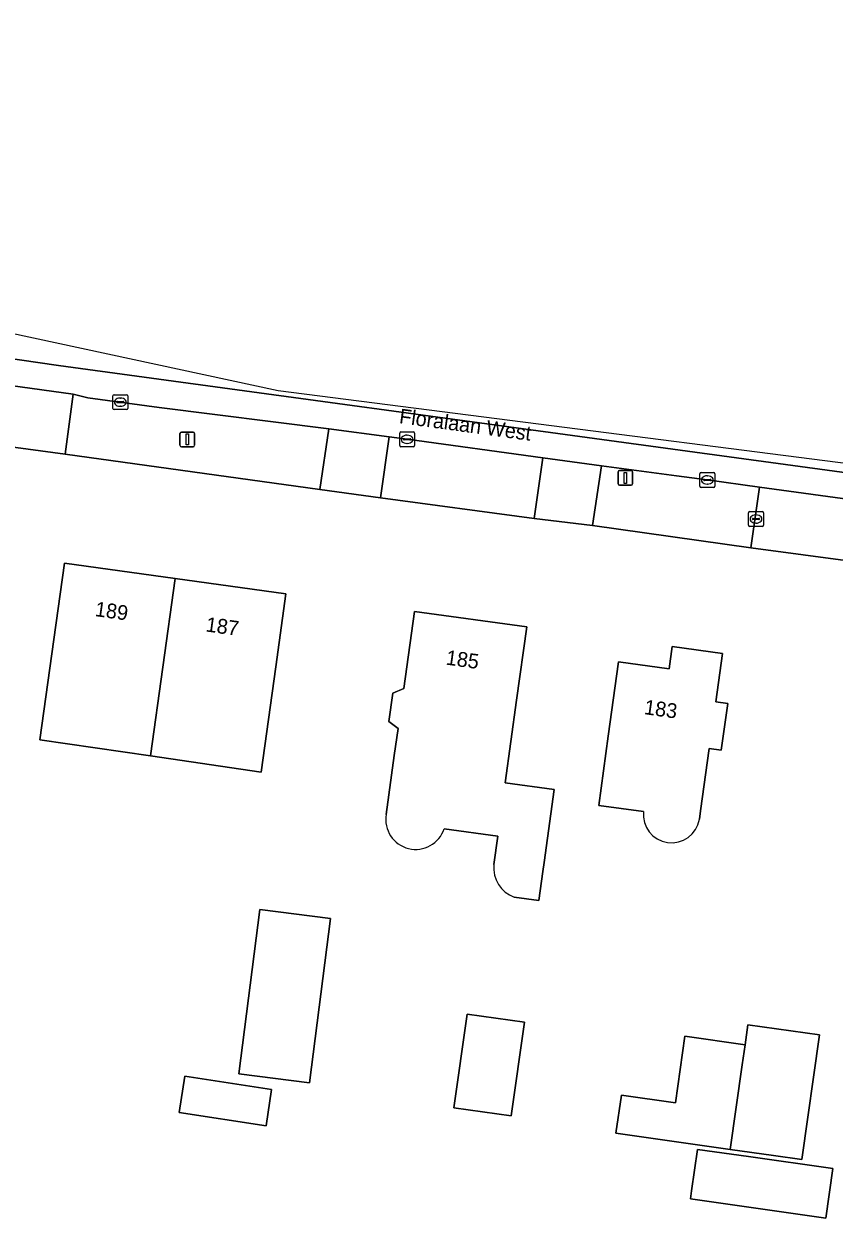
# Model space of a CAD drawing. Extents: x 161483 to 162250, y 379484 to 380833.
# Drawn here: x 161842.7 to 161897.6, y 380748.1 to 380829.1 of the extents above; entities that cross this region are included whole.
import ezdxf

# ---------------------------------------------------------------- set-up
doc = ezdxf.new("R2010")
doc.units = 0
for name, color, linetype in [('IMGEO_Brandkraan', 7, 'Continuous'), ('IMGEO_Erf', 7, 'Continuous'), ('IMGEO_Fietspad_open', 7, 'Continuous'), ('IMGEO_Kolk', 7, 'Continuous'), ('IMGEO_Lichtmast', 7, 'Continuous'), ('IMGEO_Openbare_ruimte_label', 7, 'Continuous'), ('IMGEO_Pand', 7, 'Continuous'), ('IMGEO_Pand_nummerreeks', 7, 'Continuous'), ('IMGEO_Rijbaan_lokaal_gesloten', 7, 'Continuous'), ('IMGEO_Voetpad_open', 7, 'Continuous')]:
    doc.layers.add(name, color=color, linetype=linetype)

msp = doc.modelspace()

# ---------------------------------------------------------------- linework, layer by layer
at = {"layer": 'IMGEO_Brandkraan'}
for p, q in [((161891.846, 380795.091), (161891.846, 380795.943)), ((161891.921, 380796.017), (161892.773, 380796.017)), ((161892.105, 380795.511), (161892.105, 380795.523)), ((161892.543, 380795.474), (161892.145, 380795.474)), ((161892.148, 380795.56), (161892.546, 380795.56)), ((161892.357, 380795.237), (161892.332, 380795.237)), ((161892.334, 380795.797), (161892.359, 380795.797)), ((161892.589, 380795.523), (161892.589, 380795.511)), ((161892.847, 380795.943), (161892.847, 380795.091)), ((161892.773, 380795.017), (161891.921, 380795.017))]:
    msp.add_line(p, q, dxfattribs=at)
for points in [[(161891.846, 380795.091), (161891.846, 380795.943)], [(161891.921, 380796.017), (161892.773, 380796.017)], [(161892.847, 380795.943), (161892.847, 380795.091)], [(161892.773, 380795.017), (161891.921, 380795.017)]]:
    msp.add_lwpolyline(points, dxfattribs=at)
for centre, radius, start, end in [((161891.923, 380795.941), 0.0765, 91.55205, 178.44795), ((161891.923, 380795.941), 0.0765, 91.55205, 178.44795), ((161892.145, 380795.52), 0.0403, 85.87752, 175.75265), ((161892.142, 380795.51), 0.0366, 178.93798, 274.71019), ((161892.546, 380795.517), 0.043, 264.86636, 352.45326), ((161892.55, 380795.522), 0.0386, 1.73085, 96.63898), ((161892.771, 380795.941), 0.0765, 1.55205, 88.44795), ((161892.771, 380795.941), 0.0765, 1.55205, 88.44795), ((161891.923, 380795.093), 0.0765, 181.55205, 268.44795), ((161891.923, 380795.093), 0.0765, 181.55205, 268.44795), ((161892.771, 380795.093), 0.0765, 271.55205, 358.44795), ((161892.771, 380795.093), 0.0765, 271.55205, 358.44795)]:
    msp.add_arc(centre, radius, start, end, dxfattribs=at)
for centre, major_axis, ratio, start_param, end_param in [((161892.333, 380795.517), (-0.387, 0.002), 0.722429, 4.712389, 7.853982), ((161892.358, 380795.517), (-0.39, 0.002), 0.717154, 1.570796, 4.712389)]:
    msp.add_ellipse(centre, major_axis=major_axis, ratio=ratio, start_param=start_param, end_param=end_param, dxfattribs=at)
at = {"layer": 'IMGEO_Erf'}
for points in [[(161947.776, 380785.993), (161943.772, 380786.523), (161932.427, 380787.968), (161928.533, 380788.644), (161917.439, 380790.128), (161913.448, 380790.714), (161899.09, 380792.619), (161891.993, 380793.568), (161881.272, 380795.068), (161877.324, 380795.561), (161866.903, 380796.964), (161862.786, 380797.518), (161845.524, 380799.914), (161837.657, 380800.986)], [(161867.284, 380775.488), (161867.837, 380779.481), (161868.089, 380781.301), (161867.463, 380781.788), (161867.731, 380783.715), (161868.492, 380784.025), (161869.216, 380789.248), (161876.81, 380788.195), (161876.123, 380783.243), (161875.346, 380777.637)], [(161884.718, 380775.679), (161881.69, 380776.099), (161882.339, 380780.782), (161883.04, 380785.836), (161886.458, 380785.361), (161886.668, 380786.872), (161890.078, 380786.399), (161889.622, 380783.111), (161890.436, 380782.998), (161889.999, 380779.842), (161889.175, 380779.957), (161888.587, 380775.717)], [(161875.346, 380777.637), (161878.675, 380777.176), (161877.989, 380772.224), (161877.906, 380771.621), (161877.634, 380769.645), (161875.969, 380769.875)], [(161888.587, 380775.717), (161888.509, 380775.153)], [(161874.578, 380772.081), (161874.845, 380774.016), (161871.216, 380774.518)]]:
    msp.add_lwpolyline(points, dxfattribs=at)
for points in [[(161859.81, 380785.497), (161858.818, 380778.346), (161851.32, 380779.45), (161843.819, 380780.554), (161844.762, 380787.352), (161845.481, 380792.531), (161852.988, 380791.49), (161860.496, 380790.449)], [(161862.083, 380757.292), (161857.301, 380757.904), (161858.726, 380769.034), (161863.508, 380768.422)], [(161875.767, 380755.034), (161871.873, 380755.587), (161872.775, 380761.943), (161876.67, 380761.39)], [(161895.46, 380752.079), (161893.543, 380752.352), (161890.604, 380752.769), (161882.861, 380753.868), (161883.229, 380756.457), (161886.893, 380755.937), (161887.534, 380760.448), (161891.612, 380759.869), (161891.805, 380761.223), (161896.661, 380760.534)], [(161859.143, 380754.376), (161853.256, 380755.282), (161853.635, 380757.742), (161859.522, 380756.836)], [(161897.549, 380751.471), (161897.071, 380748.109), (161887.912, 380749.411), (161887.989, 380749.951), (161888.39, 380752.773), (161891.831, 380752.284)]]:
    msp.add_lwpolyline(points, close=True, dxfattribs=at)
for centre, radius, start, end in [((161869.285, 380775.143), 2.03, 170.2125, 342.07187), ((161886.622, 380775.476), 1.915, 173.92875, 350.27258), ((161876.696, 380771.875), 2.128, 174.44816, 250.01905)]:
    msp.add_arc(centre, radius, start, end, dxfattribs=at)
at = {"layer": 'IMGEO_Fietspad_open'}
for points in [[(161944.816, 380792.342), (161887.22, 380800.191), (161845.075, 380805.921), (161833.402, 380807.634), (161828.42, 380808.407)], [(161838.216, 380805.069), (161846.078, 380803.976), (161847.071, 380803.724), (161851.906, 380803.091), (161863.408, 380801.636), (161867.481, 380801.087), (161868.7, 380800.923), (161877.899, 380799.667), (161881.879, 380799.119), (161886.971, 380798.442), (161889.046, 380798.166), (161892.587, 380797.666), (161899.699, 380796.708), (161912.838, 380794.902), (161914.017, 380794.744), (161918.055, 380794.201), (161929.077, 380792.694), (161932.993, 380792.169), (161935.206, 380791.883), (161944.345, 380790.629), (161948.316, 380790.073)]]:
    msp.add_lwpolyline(points, dxfattribs=at)
at = {"layer": 'IMGEO_Kolk'}
for p, q in [((161848.765, 380803.017), (161848.765, 380803.869)), ((161848.84, 380803.943), (161849.692, 380803.943)), ((161849.024, 380803.437), (161849.024, 380803.449)), ((161849.462, 380803.4), (161849.064, 380803.4)), ((161849.067, 380803.486), (161849.465, 380803.486)), ((161849.253, 380803.723), (161849.278, 380803.723)), ((161849.508, 380803.449), (161849.508, 380803.437)), ((161849.766, 380803.869), (161849.766, 380803.017)), ((161849.692, 380802.943), (161848.84, 380802.943)), ((161849.276, 380803.163), (161849.251, 380803.163)), ((161868.203, 380800.496), (161868.203, 380801.348)), ((161868.278, 380801.422), (161869.13, 380801.422)), ((161868.462, 380800.916), (161868.462, 380800.928)), ((161868.505, 380800.965), (161868.903, 380800.965)), ((161868.691, 380801.202), (161868.716, 380801.202)), ((161868.946, 380800.928), (161868.946, 380800.916)), ((161869.204, 380801.348), (161869.204, 380800.496)), ((161869.13, 380800.422), (161868.278, 380800.422)), ((161868.9, 380800.879), (161868.502, 380800.879)), ((161868.714, 380800.642), (161868.689, 380800.642)), ((161888.549, 380797.739), (161888.549, 380798.591)), ((161888.624, 380798.665), (161889.476, 380798.665)), ((161889.55, 380798.591), (161889.55, 380797.739)), ((161889.476, 380797.665), (161888.624, 380797.665)), ((161888.808, 380798.159), (161888.808, 380798.171)), ((161889.246, 380798.122), (161888.848, 380798.122)), ((161888.851, 380798.208), (161889.249, 380798.208)), ((161889.06, 380797.885), (161889.035, 380797.885)), ((161889.037, 380798.445), (161889.062, 380798.445)), ((161889.292, 380798.171), (161889.292, 380798.159))]:
    msp.add_line(p, q, dxfattribs=at)
for points in [[(161848.765, 380803.017), (161848.765, 380803.869)], [(161848.84, 380803.943), (161849.692, 380803.943)], [(161849.766, 380803.869), (161849.766, 380803.017)], [(161849.692, 380802.943), (161848.84, 380802.943)], [(161868.203, 380800.496), (161868.203, 380801.348)], [(161868.278, 380801.422), (161869.13, 380801.422)], [(161869.204, 380801.348), (161869.204, 380800.496)], [(161869.13, 380800.422), (161868.278, 380800.422)], [(161888.549, 380797.739), (161888.549, 380798.591)], [(161888.624, 380798.665), (161889.476, 380798.665)], [(161889.55, 380798.591), (161889.55, 380797.739)], [(161889.476, 380797.665), (161888.624, 380797.665)]]:
    msp.add_lwpolyline(points, dxfattribs=at)
for centre, radius, start, end in [((161848.842, 380803.867), 0.0765, 91.55205, 178.44795), ((161848.842, 380803.867), 0.0765, 91.55205, 178.44795), ((161849.064, 380803.446), 0.0403, 85.87752, 175.75265), ((161849.061, 380803.436), 0.0366, 178.93798, 274.71019), ((161849.465, 380803.443), 0.043, 264.86636, 352.45326), ((161849.469, 380803.448), 0.0386, 1.73085, 96.63898), ((161849.69, 380803.867), 0.0765, 1.55205, 88.44795), ((161849.69, 380803.867), 0.0765, 1.55205, 88.44795), ((161848.842, 380803.019), 0.0765, 181.55205, 268.44795), ((161848.842, 380803.019), 0.0765, 181.55205, 268.44795), ((161849.69, 380803.019), 0.0765, 271.55205, 358.44795), ((161849.69, 380803.019), 0.0765, 271.55205, 358.44795), ((161868.28, 380801.346), 0.0765, 91.55205, 178.44795), ((161868.28, 380801.346), 0.0765, 91.55205, 178.44795), ((161868.502, 380800.925), 0.0403, 85.87752, 175.75265), ((161868.499, 380800.915), 0.0366, 178.93798, 274.71019), ((161868.903, 380800.922), 0.043, 264.86636, 352.45326), ((161868.907, 380800.927), 0.0386, 1.73085, 96.63898), ((161869.128, 380801.346), 0.0765, 1.55205, 88.44795), ((161869.128, 380801.346), 0.0765, 1.55205, 88.44795), ((161868.28, 380800.498), 0.0765, 181.55205, 268.44795), ((161868.28, 380800.498), 0.0765, 181.55205, 268.44795), ((161869.128, 380800.498), 0.0765, 271.55205, 358.44795), ((161869.128, 380800.498), 0.0765, 271.55205, 358.44795), ((161888.626, 380798.589), 0.0765, 91.55205, 178.44795), ((161888.626, 380798.589), 0.0765, 91.55205, 178.44795), ((161889.474, 380798.589), 0.0765, 1.55205, 88.44795), ((161889.474, 380798.589), 0.0765, 1.55205, 88.44795), ((161888.626, 380797.741), 0.0765, 181.55205, 268.44795), ((161888.626, 380797.741), 0.0765, 181.55205, 268.44795), ((161888.848, 380798.168), 0.0403, 85.87752, 175.75265), ((161888.845, 380798.158), 0.0366, 178.93798, 274.71019), ((161889.249, 380798.165), 0.043, 264.86636, 352.45326), ((161889.253, 380798.17), 0.0386, 1.73085, 96.63898), ((161889.474, 380797.741), 0.0765, 271.55205, 358.44795), ((161889.474, 380797.741), 0.0765, 271.55205, 358.44795)]:
    msp.add_arc(centre, radius, start, end, dxfattribs=at)
for centre, major_axis, ratio, start_param, end_param in [((161849.252, 380803.443), (-0.387, 0.002), 0.722429, 4.712389, 7.853982), ((161849.277, 380803.443), (-0.39, 0.002), 0.717154, 1.570796, 4.712389), ((161868.69, 380800.922), (-0.387, 0.002), 0.722429, 4.712389, 7.853982), ((161868.715, 380800.922), (-0.39, 0.002), 0.717154, 1.570796, 4.712389), ((161889.036, 380798.165), (-0.387, 0.002), 0.722429, 4.712389, 7.853982), ((161889.061, 380798.165), (-0.39, 0.002), 0.717154, 1.570796, 4.712389)]:
    msp.add_ellipse(centre, major_axis=major_axis, ratio=ratio, start_param=start_param, end_param=end_param, dxfattribs=at)
at = {"layer": 'IMGEO_Lichtmast'}
for p, q in [((161853.312, 380800.515), (161853.312, 380801.315)), ((161853.312, 380801.315), (161853.312, 380800.515)), ((161853.412, 380801.415), (161854.202, 380801.415)), ((161854.202, 380801.415), (161853.412, 380801.415)), ((161854.302, 380801.315), (161854.302, 380800.515)), ((161854.302, 380800.515), (161854.302, 380801.315)), ((161854.202, 380800.415), (161853.412, 380800.415)), ((161853.412, 380800.415), (161854.202, 380800.415)), ((161882.999, 380797.906), (161882.999, 380798.706)), ((161882.999, 380798.706), (161882.999, 380797.906)), ((161883.099, 380798.806), (161883.889, 380798.806)), ((161883.889, 380798.806), (161883.099, 380798.806)), ((161883.989, 380798.706), (161883.989, 380797.906)), ((161883.989, 380797.906), (161883.989, 380798.706)), ((161883.889, 380797.806), (161883.099, 380797.806)), ((161883.099, 380797.806), (161883.889, 380797.806))]:
    msp.add_line(p, q, dxfattribs=at)
for points in [[(161853.732, 380801.29), (161853.882, 380801.29), (161853.882, 380800.54), (161853.732, 380800.54), (161853.732, 380801.29)], [(161883.419, 380798.681), (161883.569, 380798.681), (161883.569, 380797.931), (161883.419, 380797.931), (161883.419, 380798.681)]]:
    msp.add_lwpolyline(points, dxfattribs=at)
for centre, start, end in [((161853.412, 380801.315), 90, 180), ((161853.412, 380801.315), 90, 180), ((161854.202, 380801.315), 0, 90), ((161854.202, 380801.315), 360, 90), ((161853.412, 380800.515), 180, 270), ((161853.412, 380800.515), 180, 270), ((161854.202, 380800.515), 270, 0), ((161854.202, 380800.515), 270, 0), ((161883.099, 380798.706), 90, 180), ((161883.099, 380798.706), 90, 180), ((161883.889, 380798.706), 0, 90), ((161883.889, 380798.706), 360, 90), ((161883.099, 380797.906), 180, 270), ((161883.099, 380797.906), 180, 270), ((161883.889, 380797.906), 270, 0), ((161883.889, 380797.906), 270, 0)]:
    msp.add_arc(centre, 0.1, start, end, dxfattribs=at)
at = {"layer": 'IMGEO_Pand'}
for points in [[(161852.988, 380791.49), (161845.481, 380792.531), (161844.762, 380787.352), (161843.819, 380780.554), (161851.32, 380779.45)], [(161852.988, 380791.49), (161851.32, 380779.45), (161858.818, 380778.346), (161859.81, 380785.497), (161860.496, 380790.449)], [(161863.508, 380768.422), (161858.726, 380769.034), (161857.301, 380757.904), (161862.083, 380757.292)], [(161875.767, 380755.034), (161876.67, 380761.39), (161872.775, 380761.943), (161871.873, 380755.587)], [(161891.612, 380759.869), (161891.42, 380758.514), (161890.604, 380752.769), (161893.543, 380752.352), (161895.46, 380752.079), (161896.661, 380760.534), (161891.805, 380761.223)], [(161891.42, 380758.514), (161891.612, 380759.869), (161887.534, 380760.448), (161886.893, 380755.937), (161883.229, 380756.457), (161882.861, 380753.868), (161890.604, 380752.769)], [(161859.522, 380756.836), (161853.635, 380757.742), (161853.256, 380755.282), (161859.143, 380754.376)], [(161891.831, 380752.284), (161888.39, 380752.773), (161887.989, 380749.951), (161887.912, 380749.411), (161897.071, 380748.109), (161897.549, 380751.471)]]:
    msp.add_lwpolyline(points, close=True, dxfattribs=at)
for points in [[(161875.969, 380769.875), (161877.634, 380769.645), (161877.906, 380771.621), (161877.989, 380772.224), (161878.675, 380777.176), (161875.346, 380777.637), (161876.123, 380783.243), (161876.81, 380788.195), (161869.216, 380789.248), (161868.492, 380784.025), (161867.731, 380783.715), (161867.463, 380781.788), (161868.089, 380781.301), (161867.837, 380779.481), (161867.284, 380775.488)], [(161888.509, 380775.153), (161888.587, 380775.717), (161889.175, 380779.957), (161889.999, 380779.842), (161890.436, 380782.998), (161889.622, 380783.111), (161890.078, 380786.399), (161886.668, 380786.872), (161886.458, 380785.361), (161883.04, 380785.836), (161882.339, 380780.782), (161881.69, 380776.099), (161884.718, 380775.679)], [(161871.216, 380774.518), (161874.845, 380774.016), (161874.578, 380772.081)]]:
    msp.add_lwpolyline(points, dxfattribs=at)
for centre, radius, start, end in [((161869.285, 380775.143), 2.03, 170.2125, 342.07187), ((161886.622, 380775.476), 1.915, 173.92875, 350.27258), ((161876.696, 380771.875), 2.128, 174.44816, 250.01905)]:
    msp.add_arc(centre, radius, start, end, dxfattribs=at)
at = {"layer": 'IMGEO_Rijbaan_lokaal_gesloten'}
for points in [[(162235.883, 380761.117), (162225.793, 380762.232), (162195.841, 380761.556), (162155.522, 380766.113), (162152.312, 380766.476), (162100.246, 380775.712), (162094.38, 380775.785), (162063.3, 380779.137), (162022.247, 380782.773), (161914.65, 380797.204), (161859.959, 380804.218), (161826.791, 380811.355), (161807.579, 380816.265), (161765.369, 380823.138), (161719.379, 380829.094), (161719.203, 380827.684), (161722.585, 380827.174), (161725.837, 380826.617)], [(161833.402, 380807.634), (161845.075, 380805.921), (161887.22, 380800.191), (161944.816, 380792.342), (162034.971, 380780.165), (162056.354, 380777.224), (162056.903, 380777.191), (162081.643, 380775.785), (162086.162, 380775.288), (162093.056, 380774.264), (162108.19, 380772.217), (162118.907, 380770.062), (162138.618, 380766.344), (162139.976, 380766.161), (162155.313, 380764.1), (162157.657, 380763.785), (162175.214, 380761.306), (162198.829, 380757.994), (162207.5, 380757.078), (162216.737, 380756.638)]]:
    msp.add_lwpolyline(points, dxfattribs=at)
at = {"layer": 'IMGEO_Voetpad_open'}
for points in [[(161845.524, 380799.914), (161846.078, 380803.976), (161838.216, 380805.069), (161837.657, 380800.986)], [(161846.078, 380803.976), (161845.524, 380799.914), (161862.786, 380797.518), (161863.408, 380801.636), (161851.906, 380803.091), (161847.071, 380803.724)], [(161866.903, 380796.964), (161867.481, 380801.087), (161863.408, 380801.636), (161862.786, 380797.518)], [(161877.324, 380795.561), (161877.899, 380799.667), (161868.7, 380800.923), (161867.481, 380801.087), (161866.903, 380796.964)], [(161881.272, 380795.068), (161881.879, 380799.119), (161877.899, 380799.667), (161877.324, 380795.561)], [(161891.993, 380793.568), (161892.587, 380797.666), (161889.046, 380798.166), (161886.971, 380798.442), (161881.879, 380799.119), (161881.272, 380795.068)], [(161899.09, 380792.619), (161899.699, 380796.708), (161892.587, 380797.666), (161891.993, 380793.568)]]:
    msp.add_lwpolyline(points, close=True, dxfattribs=at)

# ---------------------------------------------------------------- texts
at = {"layer": 'IMGEO_Openbare_ruimte_label'}
msp.add_text('Floralaan West', height=1, rotation=352.35613, dxfattribs=at).set_placement((161868.131, 380802.018))
at = {"layer": 'IMGEO_Pand_nummerreeks'}
for s, rotation, p in [('189', 352.10464, (161847.509, 380788.939)), ('187', 352.10464, (161855.017, 380787.898)), ('185', 352.10559, (161871.288, 380785.65)), ('183', 352.08827, (161884.728, 380782.29))]:
    msp.add_text(s, height=1, rotation=rotation, dxfattribs=at).set_placement(p)

doc.saveas('drawing.dxf')
